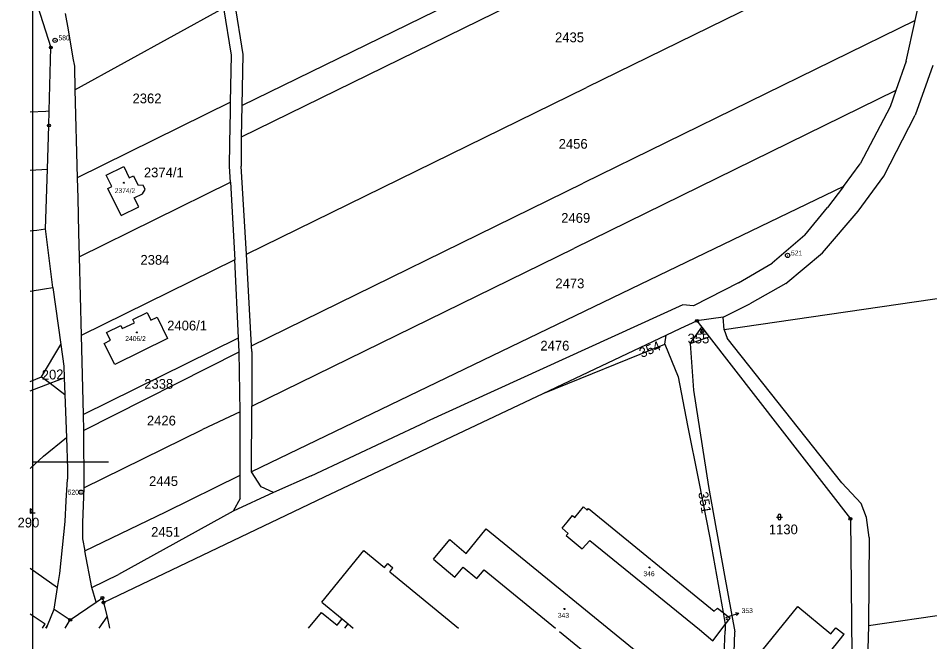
# Model space of a CAD drawing. Extents: x -565355 to -564154, y -1097649 to -1095548.
# Drawn here: x -565347.8 to -565029.6, y -1097290.5 to -1097072.9 of the extents above; entities that cross this region are included whole.
import ezdxf

# ---------------------------------------------------------------- set-up
doc = ezdxf.new("R2010")
doc.units = 0
for name, color, linetype in [('Vrstva 1', 7, 'Continuous'), ('Vrstva 16', 7, 'Continuous'), ('Vrstva 17', 7, 'Continuous'), ('Vrstva 18', 7, 'Continuous'), ('Vrstva 19', 7, 'Continuous'), ('Vrstva 24', 7, 'Continuous'), ('Vrstva 25', 7, 'Continuous'), ('Vrstva 4', 7, 'Continuous'), ('Vrstva 63', 7, 'Continuous')]:
    doc.layers.add(name, color=color, linetype=linetype)

msp = doc.modelspace()

# ---------------------------------------------------------------- linework, layer by layer
at = {"layer": 'Vrstva 1'}
for p, q in [((-565030.82, -1097038.96), (-565149.44, -1097097.1)), ((-565269.7, -1097103.36), (-565151.18, -1097045.38)), ((-565150.98, -1097056.12), (-565269.93, -1097114.34)), ((-565343.59, -1097060.63), (-565336.41, -1097083.11)), ((-565034.69, -1097073.69), (-565032.89, -1097065.5)), ((-565272.29, -1097067.43), (-565269.38, -1097085.52)), ((-565331.38, -1097071.21), (-565330.38, -1097076.97)), ((-565327.99, -1097097.88), (-565276.02, -1097069.29)), ((-565273.39, -1097085.81), (-565276.02, -1097069.29)), ((-565034.69, -1097073.69), (-565150.52, -1097130.44)), ((-565037.8, -1097087.8), (-565034.69, -1097073.69)), ((-565330.38, -1097076.97), (-565328.69, -1097086.79)), ((-565336.95, -1097105.24), (-565336.41, -1097083.11)), ((-565328.69, -1097086.79), (-565328.2, -1097089.61)), ((-565273.66, -1097102.13), (-565273.39, -1097085.81)), ((-565269.38, -1097085.52), (-565269.7, -1097103.36)), ((-565037.8, -1097087.8), (-565041.4, -1097098.15)), ((-565328.2, -1097089.61), (-565327.99, -1097097.88)), ((-565028.5, -1097089.42), (-565034.62, -1097106.71)), ((-565268.06, -1097155.24), (-565149.44, -1097097.1)), ((-565327.99, -1097097.88), (-565327.21, -1097128.57)), ((-565041.4, -1097098.15), (-565153.84, -1097153.22)), ((-565041.4, -1097098.15), (-565043.38, -1097103.85)), ((-565273.66, -1097102.13), (-565327.21, -1097128.57)), ((-565273.72, -1097105.46), (-565273.66, -1097102.13)), ((-565269.7, -1097103.36), (-565269.93, -1097114.34)), ((-565043.38, -1097103.85), (-565053.87, -1097123.7)), ((-565343.59, -1097105.53), (-565338.14, -1097105.29)), ((-565338.14, -1097105.29), (-565336.95, -1097105.24)), ((-565337.07, -1097110.28), (-565336.95, -1097105.24)), ((-565273.89, -1097116.34), (-565273.72, -1097105.46)), ((-565045.59, -1097127.97), (-565034.62, -1097106.71)), ((-565337.57, -1097125.56), (-565337.07, -1097110.28)), ((-565274.02, -1097124.57), (-565273.89, -1097116.34)), ((-565269.93, -1097114.34), (-565270.02, -1097124.49)), ((-565343.59, -1097125.91), (-565337.57, -1097125.56)), ((-565338.24, -1097146.37), (-565337.57, -1097125.56)), ((-565317.06, -1097127.61), (-565310.94, -1097124.62)), ((-565310.94, -1097124.62), (-565309.03, -1097128.53)), ((-565273.71, -1097130.03), (-565274.02, -1097124.57)), ((-565268.06, -1097155.24), (-565270.02, -1097124.49)), ((-565059.71, -1097131.55), (-565053.87, -1097123.7)), ((-565327.21, -1097128.57), (-565327.03, -1097135.61)), ((-565315.13, -1097131.57), (-565317.06, -1097127.61)), ((-565309.03, -1097128.53), (-565307.52, -1097127.83)), ((-565307.52, -1097127.83), (-565306.02, -1097131.06)), ((-565054.53, -1097140.18), (-565045.59, -1097127.97)), ((-565326.5, -1097156.11), (-565273.71, -1097130.03)), ((-565316.57, -1097132.28), (-565315.13, -1097131.57)), ((-565311.89, -1097141.76), (-565316.57, -1097132.28)), ((-565306.02, -1097131.06), (-565304.24, -1097131.16)), ((-565304.43, -1097134.16), (-565303.47, -1097132.7)), ((-565303.47, -1097132.7), (-565304.24, -1097131.16)), ((-565273.71, -1097130.03), (-565272.16, -1097157.15)), ((-565266.35, -1097187.18), (-565150.52, -1097130.44)), ((-565059.71, -1097131.55), (-565163.01, -1097181.36)), ((-565059.71, -1097131.55), (-565065.23, -1097138.95)), ((-565327.03, -1097135.61), (-565326.72, -1097147.67)), ((-565307.33, -1097135.57), (-565304.43, -1097134.16)), ((-565305.75, -1097138.74), (-565307.33, -1097135.57)), ((-565311.89, -1097141.76), (-565305.75, -1097138.74)), ((-565073.17, -1097148.55), (-565065.23, -1097138.95)), ((-565067.05, -1097154.71), (-565054.53, -1097140.18)), ((-565343.59, -1097147.02), (-565341.28, -1097146.83)), ((-565341.28, -1097146.83), (-565338.24, -1097146.37)), ((-565335.67, -1097166.83), (-565338.24, -1097146.37)), ((-565326.72, -1097147.67), (-565326.5, -1097156.11)), ((-565073.17, -1097148.55), (-565084.54, -1097158.41)), ((-565266.28, -1097208.28), (-565153.84, -1097153.22)), ((-565079.84, -1097165.42), (-565067.05, -1097154.71)), ((-565326.5, -1097156.11), (-565325.8, -1097183.64)), ((-565272.16, -1097157.15), (-565325.8, -1097183.64)), ((-565270.92, -1097184.42), (-565272.16, -1097157.15)), ((-565266.35, -1097187.18), (-565268.06, -1097155.24)), ((-564940.41, -1097158.16), (-565101.37, -1097181.57)), ((-565096.37, -1097165.2), (-565084.54, -1097158.41)), ((-565343.59, -1097168.09), (-565338.62, -1097167.3)), ((-565338.62, -1097167.3), (-565335.67, -1097166.83)), ((-565335.67, -1097166.83), (-565332.92, -1097186.78)), ((-565096.37, -1097165.2), (-565112.06, -1097173.23)), ((-565079.84, -1097165.42), (-565092.41, -1097172.49)), ((-565115.76, -1097172.86), (-565205.44, -1097213.73)), ((-565112.06, -1097173.23), (-565115.76, -1097172.86)), ((-565101.71, -1097177.19), (-565092.41, -1097172.49)), ((-565307.75, -1097178.05), (-565302.82, -1097175.57)), ((-565302.82, -1097175.57), (-565301.5, -1097178.24)), ((-565301.5, -1097178.24), (-565299.34, -1097177.19)), ((-565299.34, -1097177.19), (-565295.67, -1097184.62)), ((-565101.71, -1097177.19), (-565110.87, -1097178.47)), ((-565101.37, -1097181.57), (-565101.71, -1097177.19)), ((-565316.93, -1097182.57), (-565312.01, -1097180.12)), ((-565312.01, -1097180.12), (-565311.49, -1097181.18)), ((-565311.49, -1097181.18), (-565307.23, -1097179.14)), ((-565307.23, -1097179.14), (-565307.75, -1097178.05)), ((-565116.47, -1097181.09), (-565110.87, -1097178.47)), ((-565110.87, -1097178.47), (-565109.11, -1097180.74)), ((-565325.8, -1097183.64), (-565325.1, -1097211.18)), ((-565315.6, -1097185.28), (-565316.93, -1097182.57)), ((-565163.01, -1097181.36), (-565266.31, -1097231.16)), ((-565164.53, -1097203.82), (-565121.62, -1097183.53)), ((-565122.01, -1097186.67), (-565121.62, -1097183.53)), ((-565121.62, -1097183.53), (-565116.47, -1097181.09)), ((-565113.23, -1097186.37), (-565109.11, -1097180.74)), ((-565109.11, -1097180.74), (-565106.55, -1097184.04)), ((-565101.37, -1097181.57), (-565100.3, -1097184.54)), ((-565339.63, -1097198.05), (-565332.92, -1097186.78)), ((-565332.92, -1097186.78), (-565331.88, -1097194.35)), ((-565325.1, -1097211.18), (-565270.92, -1097184.42)), ((-565317.76, -1097186.33), (-565315.6, -1097185.28)), ((-565314.09, -1097193.68), (-565317.76, -1097186.33)), ((-565295.67, -1097184.62), (-565314.09, -1097193.68)), ((-565270.7, -1097189.27), (-565270.92, -1097184.42)), ((-565164.53, -1097203.82), (-565122.01, -1097186.67)), ((-565122.01, -1097186.67), (-565117.44, -1097198.02)), ((-565113.23, -1097186.37), (-565106.55, -1097184.04)), ((-565113.23, -1097186.37), (-565112.03, -1097202.71)), ((-565106.55, -1097184.04), (-565057.28, -1097247.6)), ((-565060.23, -1097235.05), (-565100.3, -1097184.54)), ((-565324.96, -1097216.72), (-565270.7, -1097189.27)), ((-565270.29, -1097210.24), (-565270.7, -1097189.27)), ((-565266.26, -1097189.22), (-565266.35, -1097187.18)), ((-565266.26, -1097189.22), (-565266.28, -1097208.28)), ((-565331.88, -1097194.35), (-565331.72, -1097198.35)), ((-565343.59, -1097199.69), (-565339.63, -1097198.05)), ((-565339.63, -1097198.05), (-565336.69, -1097200.28)), ((-565331.72, -1097198.35), (-565331.49, -1097204.22)), ((-565117.44, -1097198.02), (-565114.1, -1097214.99)), ((-565336.69, -1097200.28), (-565331.49, -1097204.22)), ((-565112.03, -1097202.71), (-565106.85, -1097236.33)), ((-565331.49, -1097204.22), (-565330.9, -1097219.24)), ((-565240.85, -1097239.89), (-565164.53, -1097203.82)), ((-565266.31, -1097231.16), (-565266.28, -1097208.28)), ((-565325.1, -1097211.18), (-565324.96, -1097216.72)), ((-565270.29, -1097210.24), (-565283.42, -1097216.45)), ((-565270.31, -1097232.29), (-565270.29, -1097210.24)), ((-565245.52, -1097232.56), (-565205.44, -1097213.73)), ((-565114.1, -1097214.99), (-565110.36, -1097234.04)), ((-565324.96, -1097216.72), (-565324.91, -1097236.72)), ((-565324.91, -1097236.72), (-565283.42, -1097216.45)), ((-565338.94, -1097225.75), (-565330.9, -1097219.24)), ((-565330.9, -1097219.24), (-565330.64, -1097230.12)), ((-565343.59, -1097230.05), (-565338.94, -1097225.75)), ((-565330.64, -1097230.12), (-565330.59, -1097233.72)), ((-565263.04, -1097236.38), (-565266.31, -1097231.16)), ((-565331.1, -1097241.32), (-565330.59, -1097233.72)), ((-565296.22, -1097245.16), (-565270.31, -1097232.29)), ((-565270.32, -1097240.5), (-565270.31, -1097232.29)), ((-565245.52, -1097232.56), (-565258.64, -1097238.35)), ((-565110.36, -1097234.04), (-565106.4, -1097254.24)), ((-565324.91, -1097236.72), (-565325.4, -1097248.95)), ((-565258.64, -1097238.35), (-565263.04, -1097236.38)), ((-565106.85, -1097236.33), (-565101.24, -1097267.35)), ((-565060.23, -1097235.05), (-565053.48, -1097242.24)), ((-565318.01, -1097276.83), (-565240.85, -1097239.89)), ((-565258.64, -1097238.35), (-565272.77, -1097244.93)), ((-565270.32, -1097240.5), (-565272.77, -1097244.93)), ((-565331.39, -1097248.52), (-565331.1, -1097241.32)), ((-565153.54, -1097247.14), (-565150.5, -1097243.41)), ((-565150.5, -1097243.41), (-565149.13, -1097244.53)), ((-565149.13, -1097244.53), (-565148.66, -1097243.97)), ((-565148.66, -1097243.97), (-565104.85, -1097279.81)), ((-565051.68, -1097247.08), (-565053.48, -1097242.24)), ((-565324.55, -1097258.75), (-565296.22, -1097245.16)), ((-565272.77, -1097244.93), (-565312.81, -1097267.05)), ((-565156.2, -1097248.73), (-565154.34, -1097246.45)), ((-565154.34, -1097246.45), (-565153.54, -1097247.14)), ((-565050.72, -1097254.14), (-565051.68, -1097247.08)), ((-565333.28, -1097266.65), (-565331.39, -1097248.52)), ((-565325.4, -1097248.95), (-565325.34, -1097254.54)), ((-565157.91, -1097250.85), (-565156.2, -1097248.73)), ((-565057.28, -1097247.6), (-565056.78, -1097294.75)), ((-565191.43, -1097259.68), (-565184.4, -1097251.09)), ((-565184.4, -1097251.09), (-565122.49, -1097301.54)), ((-565157.91, -1097250.85), (-565155.85, -1097252.67)), ((-565156.46, -1097253.41), (-565155.85, -1097252.67)), ((-565156.46, -1097253.41), (-565150.88, -1097258.1)), ((-565325.34, -1097254.54), (-565324.55, -1097258.75)), ((-565202.87, -1097261.71), (-565197.17, -1097254.75)), ((-565197.17, -1097254.75), (-565191.43, -1097259.68)), ((-565150.88, -1097258.1), (-565148.25, -1097255.18)), ((-565148.25, -1097255.18), (-565109.98, -1097286.18)), ((-565106.4, -1097254.24), (-565101.74, -1097280.3)), ((-565050.72, -1097254.14), (-565050.92, -1097284.89)), ((-565322.15, -1097271.51), (-565324.55, -1097258.75)), ((-565241.85, -1097276.61), (-565227.15, -1097258.62)), ((-565227.15, -1097258.62), (-565219.88, -1097264.56)), ((-564863.89, -1097257.7), (-565050.92, -1097284.89)), ((-565219.88, -1097264.56), (-565218.77, -1097263.2)), ((-565218.77, -1097263.2), (-565217.02, -1097264.64)), ((-565202.87, -1097261.71), (-565195.36, -1097267.99)), ((-565343.59, -1097264.77), (-565334.08, -1097271.58)), ((-565218.08, -1097266.04), (-565217.02, -1097264.64)), ((-565218.08, -1097266.04), (-565194.05, -1097285.69)), ((-565195.36, -1097267.99), (-565192.5, -1097264.48)), ((-565192.5, -1097264.48), (-565187.69, -1097268.41)), ((-565187.69, -1097268.41), (-565185.19, -1097265.36)), ((-565185.19, -1097265.36), (-565160.24, -1097285.69)), ((-565334.08, -1097271.58), (-565333.28, -1097266.65)), ((-565322.15, -1097271.51), (-565312.81, -1097267.05)), ((-565101.24, -1097267.35), (-565097.67, -1097287.04)), ((-565335.29, -1097279.08), (-565334.08, -1097271.58)), ((-565320.61, -1097276.69), (-565322.15, -1097271.51)), ((-565320.61, -1097276.69), (-565318.41, -1097275.19)), ((-565318.41, -1097275.19), (-565318.01, -1097276.83)), ((-565337.56, -1097284.8), (-565335.29, -1097279.08)), ((-565335.29, -1097279.08), (-565329.63, -1097282.84)), ((-565329.63, -1097282.84), (-565320.61, -1097276.69)), ((-565318.01, -1097276.83), (-565316.81, -1097281.83)), ((-565241.85, -1097276.61), (-565234.72, -1097282.48)), ((-565104.85, -1097279.81), (-565103.64, -1097278.76)), ((-565103.64, -1097278.76), (-565101.74, -1097280.3)), ((-565098.28, -1097306.01), (-565075.67, -1097278.22)), ((-565075.67, -1097278.22), (-565064.1, -1097287.66)), ((-565316.81, -1097281.83), (-565315.96, -1097285.69)), ((-565246.41, -1097285.69), (-565241.98, -1097280.27)), ((-565241.98, -1097280.27), (-565236.51, -1097284.7)), ((-565101.74, -1097280.3), (-565099.3, -1097282.28)), ((-565101.74, -1097280.3), (-565100.99, -1097284.5)), ((-565100.99, -1097284.5), (-565099.3, -1097282.28)), ((-565337.98, -1097285.69), (-565337.56, -1097284.8)), ((-565331.39, -1097285.69), (-565329.63, -1097282.84)), ((-565236.51, -1097284.7), (-565234.72, -1097282.48)), ((-565234.72, -1097282.48), (-565232.63, -1097284.26)), ((-565233.8, -1097285.69), (-565232.63, -1097284.26)), ((-565232.63, -1097284.26), (-565230.88, -1097285.69)), ((-565105.26, -1097290.14), (-565100.99, -1097284.5)), ((-565100.99, -1097284.5), (-565100.99, -1097286.66)), ((-565050.92, -1097284.89), (-565051.35, -1097297.19)), ((-565158.82, -1097286.85), (-565134.08, -1097307.01)), ((-565109.98, -1097286.18), (-565105.26, -1097290.14)), ((-565101.99, -1097310.57), (-565100.99, -1097286.66)), ((-565098.28, -1097306.01), (-565097.67, -1097287.04)), ((-565064.1, -1097287.66), (-565062.39, -1097285.56)), ((-565062.39, -1097285.56), (-565059.5, -1097287.83)), ((-565061.23, -1097290.07), (-565059.5, -1097287.83)), ((-565098.59, -1097335.9), (-565061.23, -1097290.07))]:
    msp.add_line(p, q, dxfattribs=at)
at = {"layer": 'Vrstva 16'}
for p, q in [((-565100.79, -1097282), (-565099.09, -1097281.43)), ((-565099.09, -1097281.43), (-565096.25, -1097280.47))]:
    msp.add_line(p, q, dxfattribs=at)
msp.add_lwpolyline([(-565097.35, -1097280.32), (-565096.25, -1097280.47), (-565097.04, -1097281.27)], dxfattribs=at)
at = {"layer": 'Vrstva 24'}
for centre, radius in [((-565334.94, -1097080.59), 0.75), ((-565334.94, -1097080.59), 0.0327), ((-565336.41, -1097083.11), 0.5), ((-565336.41, -1097083.11), 0.5), ((-565336.41, -1097083.11), 0.0327), ((-565336.41, -1097083.11), 0.0327), ((-565337.07, -1097110.28), 0.5), ((-565337.07, -1097110.28), 0.5), ((-565337.07, -1097110.28), 0.0327), ((-565337.07, -1097110.28), 0.0327), ((-565079.2, -1097155.66), 0.75), ((-565079.2, -1097155.66), 0.0327), ((-565110.87, -1097178.47), 0.5), ((-565110.87, -1097178.47), 0.5), ((-565110.87, -1097178.47), 0.0327), ((-565110.87, -1097178.47), 0.0327), ((-565325.86, -1097238.27), 0.75), ((-565325.86, -1097238.27), 0.0327), ((-565057.28, -1097247.6), 0.5), ((-565057.28, -1097247.6), 0.5), ((-565057.28, -1097247.6), 0.0327), ((-565057.28, -1097247.6), 0.0327), ((-565318.41, -1097275.19), 0.5), ((-565318.41, -1097275.19), 0.5), ((-565318.41, -1097275.19), 0.0327), ((-565318.41, -1097275.19), 0.0327), ((-565318.01, -1097276.83), 0.5), ((-565318.01, -1097276.83), 0.5), ((-565318.01, -1097276.83), 0.0327), ((-565318.01, -1097276.83), 0.0327), ((-565329.63, -1097282.84), 0.5), ((-565329.63, -1097282.84), 0.5), ((-565329.63, -1097282.84), 0.0327), ((-565329.63, -1097282.84), 0.0327)]:
    msp.add_circle(centre, radius, dxfattribs=at)
at = {"layer": 'Vrstva 25'}
for p, q in [((-565109.78, -1097182.26), (-565108.38, -1097182.26)), ((-565109.43, -1097182.61), (-565109.43, -1097181.91)), ((-565108.73, -1097182.61), (-565108.73, -1097181.91)), ((-565341.94, -1097245.61), (-565343.59, -1097245.61)), ((-565083.03, -1097246.94), (-565081.03, -1097246.94)), ((-565082.53, -1097247.44), (-565082.53, -1097246.44)), ((-565081.53, -1097247.44), (-565081.53, -1097246.44))]:
    msp.add_line(p, q, dxfattribs=at)
msp.add_lwpolyline([(-565343.59, -1097244.12), (-565343.59, -1097245.6)], dxfattribs=at)
for centre in [(-565310.91, -1097130.28), (-565306.36, -1097182.54), (-565127.37, -1097264.55), (-565157.12, -1097279.04), (-565100.38, -1097282.6)]:
    msp.add_circle(centre, 0.175, dxfattribs=at)
for centre, radius, start, end in [((-565109.08, -1097181.91), 0.35, 0, 180), ((-565109.08, -1097182.61), 0.35, 180, 0), ((-565343.69, -1097244.86), 0.75, 277.6623, 82.3377), ((-565082.03, -1097246.44), 0.5, 0, 180), ((-565082.03, -1097247.44), 0.5, 180, 0)]:
    msp.add_arc(centre, radius, start, end, dxfattribs=at)
at = {"layer": 'Vrstva 4'}
for p, q in [((-565336.69, -1097200.28), (-565331.72, -1097198.35)), ((-565343.59, -1097202.96), (-565336.69, -1097200.28)), ((-565343.59, -1097280.76), (-565338.39, -1097284.24)), ((-565319.54, -1097285.69), (-565316.81, -1097281.83)), ((-565339.32, -1097285.69), (-565338.39, -1097284.24)), ((-565338.13, -1097285.69), (-565337.56, -1097284.8))]:
    msp.add_line(p, q, dxfattribs=at)
at = {"layer": 'Vrstva 63'}
for p, q in [((-565342.77, -1095547.8), (-565342.77, -1097647.8)), ((-565316.33, -1097227.8), (-565342.77, -1097227.8))]:
    msp.add_line(p, q, dxfattribs=at)

# ---------------------------------------------------------------- texts
at = {"layer": 'Vrstva 16'}
msp.add_text('353', height=1.7, dxfattribs=at).set_placement((-565095.25, -1097280.47))
at = {"layer": 'Vrstva 17'}
for s, p in [('580', (-565333.75, -1097080.58)), ('521', (-565078.01, -1097155.65)), ('520', (-565330.53, -1097239.12))]:
    msp.add_text(s, height=1.7, dxfattribs=at).set_placement(p)
at = {"layer": 'Vrstva 18'}
for s, p in [('2435', (-565160.39, -1097081.25)), ('2362', (-565307.9, -1097102.56)), ('2456', (-565159.13, -1097118.41)), ('2374/1', (-565303.93, -1097128.4)), ('2469', (-565158.24, -1097144.26)), ('2384', (-565305.13, -1097158.89)), ('2473', (-565160.27, -1097167.11)), ('2406/1', (-565295.8, -1097181.82)), ('355', (-565114.12, -1097186.35)), ('2476', (-565165.51, -1097188.85)), ('2338', (-565303.81, -1097202.18)), ('2426', (-565302.88, -1097214.99)), ('2445', (-565302.12, -1097236.12)), ('290', (-565348.03, -1097250.59)), ('2451', (-565301.4, -1097253.84)), ('1130', (-565085.75, -1097252.96))]:
    msp.add_text(s, height=3.4, dxfattribs=at).set_placement(p)
for s, rotation, p in [('354', 23.373, (-565130.1, -1097191.47)), ('202', 2.0525, (-565339.51, -1097199.08)), ('351', 279.486, (-565110.41, -1097238.43))]:
    msp.add_text(s, height=3.4, rotation=rotation, dxfattribs=at).set_placement(p)
at = {"layer": 'Vrstva 19'}
for s, height, p in [('2374/2', 1.7, (-565314.12, -1097133.9)), ('2406/2', 1.7, (-565310.44, -1097185.52)), ('346', 1.7, (-565129.54, -1097267.6)), ('343', 1.7, (-565159.42, -1097282.1)), ('353', 0.1, (-565100.88, -1097282))]:
    msp.add_text(s, height=height, dxfattribs=at).set_placement(p)

doc.saveas('drawing.dxf')
